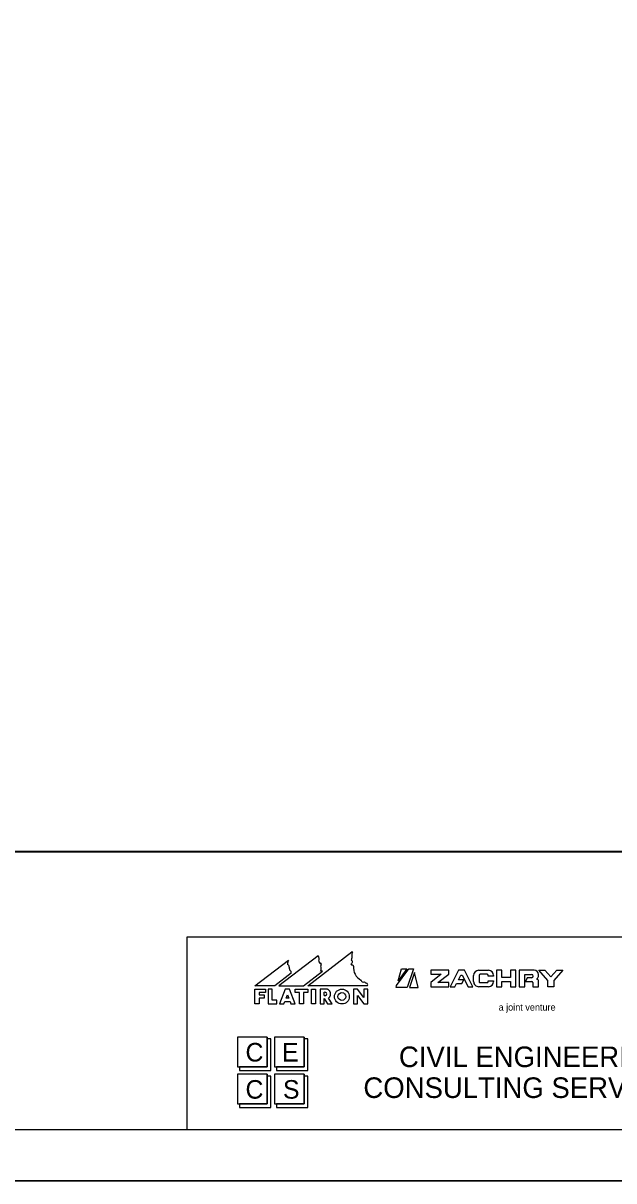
# Model space of a CAD drawing. Extents: x -2251 to 10196, y -13470 to 1199.
# Drawn here: x 6234 to 6521, y -10426 to -9863 of the extents above; entities that cross this region are included whole.
import ezdxf

# ---------------------------------------------------------------- set-up
doc = ezdxf.new("R2010")
doc.units = 0
for name, color, linetype in [('Level 3', 7, 'Continuous'), ('RD_SHT_Bndy', 7, 'Continuous'), ('RD_SHT_Iplotshp', 7, 'Continuous'), ('RD_SHT_Logo', 7, 'Continuous'), ('RD_SHT_Misc1', 7, 'Continuous'), ('RD_SHT_Snap', 7, 'Continuous'), ('RD_SHT_TX', 7, 'Continuous'), ('RD_TX_RoadID', 7, 'Continuous')]:
    doc.layers.add(name, color=color, linetype=linetype)

msp = doc.modelspace()

# ---------------------------------------------------------------- linework, layer by layer
at = {"layer": 'Level 3'}
msp.add_line((6465.07, -10363.99), (6465.07, -10363.99), dxfattribs=at)
msp.add_line((6465.07, -10363.99), (6465.07, -10363.99), dxfattribs=at)
msp.add_line((6465.07, -10363.99), (6465.07, -10363.99), dxfattribs=at)
msp.add_line((6465.07, -10363.99), (6465.07, -10363.99), dxfattribs=at)
at = {"layer": 'RD_SHT_Bndy'}
for p, q in [((5103.1, -10400.65), (6778.1, -10400.65)), ((6791.65, -10425.65), (5031.65, -10425.65))]:
    msp.add_line(p, q, dxfattribs=at)
msp.add_lwpolyline([(5153.4, -9401.26), (6731.08, -9401.26), (6731.08, -10265.57), (5153.4, -10265.57)], close=True, dxfattribs=at)
at = {"layer": 'RD_SHT_Iplotshp'}
msp.add_lwpolyline([(4996.65, -9325.65), (6796.65, -9325.65), (6796.65, -10425.65), (4996.65, -10425.65)], close=True, dxfattribs=at)
at = {"layer": 'RD_SHT_Logo'}
for p, q in [((6372.32, -10330.86), (6393.74, -10314.44)), ((6346.7, -10330.86), (6362.98, -10318.38)), ((6377.35, -10316.27), (6358.31, -10330.86)), ((6364.27, -10324.74), (6356.29, -10330.86)), ((6370.3, -10330.86), (6379.48, -10323.82)), ((6415.56, -10330.77), (6421.47, -10322.59)), ((6420.48, -10322.59), (6416.24, -10328.47)), ((6416.24, -10328.47), (6417.96, -10322.59)), ((6417.96, -10322.59), (6420.48, -10322.59)), ((6423.82, -10322.59), (6420.68, -10331.76)), ((6421.47, -10322.59), (6423.82, -10322.59)), ((6424.24, -10324.44), (6421.74, -10331.76)), ((6425.99, -10331.76), (6424.24, -10324.44)), ((6440.93, -10323.35), (6432.22, -10323.35)), ((6432.22, -10323.35), (6432.22, -10325.3)), ((6437.2, -10325.3), (6432.22, -10329.24)), ((6432.22, -10325.3), (6437.2, -10325.3)), ((6435.63, -10329.35), (6440.93, -10325.16)), ((6440.93, -10325.16), (6440.93, -10323.35)), ((6445.58, -10323.35), (6441.53, -10331.3)), ((6445.57, -10327.99), (6446.71, -10325.75)), ((6448.58, -10323.35), (6445.58, -10323.35)), ((6446.71, -10325.75), (6447.44, -10325.75)), ((6447.44, -10325.75), (6450.27, -10331.3)), ((6452.63, -10331.3), (6448.58, -10323.35)), ((6452.94, -10328.8), (6452.94, -10325.85)), ((6455.44, -10323.35), (6460.18, -10323.35)), ((6455.64, -10325.8), (6455.64, -10328.85)), ((6459.48, -10325.3), (6456.14, -10325.3)), ((6459.98, -10326.15), (6459.98, -10325.8)), ((6462.68, -10326.15), (6459.98, -10326.15)), ((6462.68, -10325.85), (6462.68, -10326.15)), ((6466.62, -10323.35), (6464.02, -10323.35)), ((6464.02, -10323.35), (6464.02, -10331.3)), ((6466.62, -10326.8), (6466.62, -10323.35)), ((6470.9, -10326.8), (6466.62, -10326.8)), ((6470.9, -10323.35), (6470.9, -10326.8)), ((6473.51, -10323.35), (6470.9, -10323.35)), ((6473.5, -10331.3), (6473.51, -10323.35)), ((6482.43, -10323.35), (6475.13, -10323.35)), ((6475.13, -10323.35), (6475.13, -10331.3)), ((6477.83, -10331.3), (6477.83, -10325.31)), ((6477.83, -10325.31), (6481.07, -10325.31)), ((6479.03, -10326.97), (6478.11, -10328.77)), ((6481.07, -10326.97), (6479.03, -10326.97)), ((6483.68, -10327.6), (6483.68, -10327.47)), ((6484.43, -10326.36), (6484.43, -10325.35)), ((6484.68, -10323.35), (6487.64, -10323.35)), ((6489.08, -10328.24), (6484.68, -10323.35)), ((6487.64, -10323.35), (6490.48, -10326.51)), ((6490.48, -10326.51), (6493.32, -10323.35)), ((6496.28, -10323.35), (6491.88, -10328.24)), ((6493.32, -10323.35), (6496.28, -10323.35)), ((6356.29, -10330.86), (6346.7, -10330.86)), ((6346.72, -10339.7), (6346.72, -10332.5)), ((6346.72, -10332.5), (6351.82, -10332.5)), ((6351.82, -10332.5), (6351.82, -10334.15)), ((6355.12, -10332.5), (6353.17, -10332.5)), ((6353.17, -10332.5), (6353.17, -10339.7)), ((6355.12, -10337.9), (6355.12, -10332.5)), ((6358.31, -10330.86), (6370.3, -10330.86)), ((6361.42, -10332.5), (6358.65, -10339.71)), ((6363.52, -10332.5), (6361.42, -10332.5)), ((6366.28, -10339.71), (6363.52, -10332.5)), ((6366.22, -10334.15), (6366.22, -10332.5)), ((6366.22, -10332.5), (6372.37, -10332.5)), ((6401.19, -10330.86), (6372.32, -10330.86)), ((6372.37, -10332.5), (6372.37, -10334.15)), ((6374.17, -10339.71), (6374.17, -10332.5)), ((6374.17, -10332.5), (6376.12, -10332.5)), ((6376.12, -10332.5), (6376.12, -10339.71)), ((6381.8, -10332.5), (6378.38, -10332.5)), ((6378.38, -10332.5), (6378.38, -10339.71)), ((6396.52, -10332.5), (6394.57, -10332.5)), ((6394.57, -10332.5), (6394.57, -10339.71)), ((6399.67, -10336.53), (6396.52, -10332.5)), ((6401.62, -10332.5), (6399.67, -10332.5)), ((6399.67, -10332.5), (6399.67, -10336.53)), ((6401.62, -10339.71), (6401.62, -10332.5)), ((6415.27, -10331.76), (6415.56, -10330.77)), ((6420.68, -10331.76), (6415.27, -10331.76)), ((6421.74, -10331.76), (6425.99, -10331.76)), ((6432.22, -10329.24), (6432.22, -10331.3)), ((6432.22, -10331.3), (6440.93, -10331.3)), ((6440.93, -10329.35), (6435.63, -10329.35)), ((6440.93, -10331.3), (6440.93, -10329.35)), ((6441.53, -10331.3), (6443.88, -10331.3)), ((6443.88, -10331.3), (6444.65, -10329.79)), ((6444.65, -10329.79), (6447.23, -10329.79)), ((6448.15, -10327.99), (6445.57, -10327.99)), ((6447.23, -10329.79), (6448.15, -10327.99)), ((6450.27, -10331.3), (6452.63, -10331.3)), ((6460.18, -10331.3), (6455.44, -10331.3)), ((6456.14, -10329.35), (6459.48, -10329.35)), ((6459.98, -10328.5), (6462.68, -10328.5)), ((6459.98, -10328.85), (6459.98, -10328.5)), ((6462.68, -10328.5), (6462.68, -10328.8)), ((6464.02, -10331.3), (6466.62, -10331.3)), ((6466.62, -10331.3), (6466.62, -10328.8)), ((6466.62, -10328.8), (6470.9, -10328.8)), ((6470.9, -10328.8), (6470.9, -10331.3)), ((6470.9, -10331.3), (6473.5, -10331.3)), ((6475.13, -10331.3), (6477.83, -10331.3)), ((6478.11, -10328.77), (6481.24, -10328.77)), ((6481.74, -10329.27), (6481.74, -10331.3)), ((6481.74, -10331.3), (6484.54, -10331.3)), ((6484.54, -10331.3), (6484.54, -10328.76)), ((6489.08, -10331.3), (6489.08, -10328.24)), ((6491.88, -10331.3), (6489.08, -10331.3)), ((6491.88, -10328.24), (6491.88, -10331.3)), ((6351.82, -10334.15), (6348.67, -10334.15)), ((6348.67, -10334.15), (6348.67, -10335.21)), ((6348.67, -10335.21), (6351.22, -10335.21)), ((6351.22, -10336.86), (6348.67, -10336.86)), ((6348.67, -10336.86), (6348.67, -10339.7)), ((6351.22, -10335.21), (6351.22, -10336.86)), ((6357.37, -10337.9), (6355.12, -10337.9)), ((6357.37, -10339.71), (6357.37, -10337.9)), ((6360.74, -10339.71), (6361.2, -10338.51)), ((6361.2, -10338.51), (6363.74, -10338.51)), ((6361.83, -10336.86), (6362.47, -10335.2)), ((6363.1, -10336.86), (6361.83, -10336.86)), ((6362.47, -10335.2), (6363.1, -10336.86)), ((6363.74, -10338.51), (6364.2, -10339.71)), ((6368.32, -10334.15), (6366.22, -10334.15)), ((6368.32, -10339.71), (6368.32, -10334.15)), ((6372.37, -10334.15), (6370.27, -10334.15)), ((6370.27, -10334.15), (6370.27, -10339.71)), ((6380.33, -10335.66), (6380.33, -10334.01)), ((6380.33, -10339.71), (6380.33, -10337.02)), ((6380.33, -10337.02), (6381.94, -10339.71)), ((6384.16, -10339.71), (6382.43, -10336.82)), ((6396.52, -10339.71), (6396.52, -10335.67)), ((6396.52, -10335.67), (6399.67, -10339.71)), ((6348.67, -10339.7), (6346.72, -10339.7)), ((6353.17, -10339.7), (6357.37, -10339.71)), ((6358.65, -10339.71), (6360.74, -10339.71)), ((6364.2, -10339.71), (6366.28, -10339.71)), ((6370.27, -10339.71), (6368.32, -10339.71)), ((6376.12, -10339.71), (6374.17, -10339.71)), ((6378.38, -10339.71), (6380.33, -10339.71)), ((6381.94, -10339.71), (6384.16, -10339.71)), ((6394.57, -10339.71), (6396.52, -10339.71)), ((6399.67, -10339.71), (6401.62, -10339.71)), ((6352.67, -10355.79), (6338.28, -10355.79)), ((6338.28, -10355.79), (6338.28, -10370.23)), ((6352.67, -10370.23), (6352.67, -10355.79)), ((6352.67, -10355.79), (6352.67, -10370.23)), ((6354.48, -10356.7), (6352.67, -10356.7)), ((6354.48, -10372.03), (6354.48, -10356.7)), ((6370.67, -10355.79), (6356.27, -10355.79)), ((6356.27, -10355.79), (6356.27, -10370.23)), ((6370.67, -10370.23), (6370.67, -10355.79)), ((6370.67, -10355.79), (6370.67, -10370.23)), ((6372.48, -10356.7), (6370.67, -10356.7)), ((6372.48, -10372.03), (6372.48, -10356.7)), ((6338.28, -10370.23), (6352.67, -10370.23)), ((6352.67, -10370.23), (6339.17, -10370.23)), ((6339.17, -10370.23), (6339.17, -10372.03)), ((6339.17, -10372.03), (6354.48, -10372.03)), ((6356.27, -10370.23), (6370.67, -10370.23)), ((6370.67, -10370.23), (6357.18, -10370.23)), ((6357.18, -10370.23), (6357.18, -10372.03)), ((6357.18, -10372.03), (6372.48, -10372.03)), ((6352.67, -10373.84), (6338.28, -10373.84)), ((6338.28, -10373.84), (6338.28, -10388.27)), ((6352.67, -10388.27), (6352.67, -10373.84)), ((6352.67, -10373.84), (6352.67, -10388.27)), ((6354.48, -10374.74), (6352.67, -10374.74)), ((6354.48, -10390.07), (6354.48, -10374.74)), ((6370.67, -10373.84), (6356.27, -10373.84)), ((6356.27, -10373.84), (6356.27, -10388.27)), ((6370.67, -10388.27), (6370.67, -10373.84)), ((6370.67, -10373.84), (6370.67, -10388.27)), ((6372.48, -10374.74), (6370.67, -10374.74)), ((6372.48, -10390.07), (6372.48, -10374.74)), ((6338.28, -10388.27), (6352.67, -10388.27)), ((6352.67, -10388.27), (6339.17, -10388.27)), ((6339.17, -10388.27), (6339.17, -10390.07)), ((6356.27, -10388.27), (6370.67, -10388.27)), ((6370.67, -10388.27), (6357.18, -10388.27)), ((6357.18, -10388.27), (6357.18, -10390.07)), ((6339.17, -10390.07), (6354.48, -10390.07)), ((6357.18, -10390.07), (6372.48, -10390.07))]:
    msp.add_line(p, q, dxfattribs=at)
for radius in [3.6, 1.9]:
    msp.add_circle((6388.95, -10336.1), radius, dxfattribs=at)
for centre, radius, start, end in [((6397.87, -10316.34), 4.17, 156.4699, 195.3053), ((6393.86, -10314.6), 0.2, 336.4699, 127.4657), ((6366.29, -10320.12), 3.74, 152.2252, 185.8662), ((6362.1, -10321.62), 1.21, 351.6466, 67.1294), ((6364.29, -10321.94), 1, 171.6466, 221.9371), ((6375.05, -10318.02), 2.89, 342.0343, 37.2653), ((6377.99, -10318.97), 0.2, 162.0343, 220.8638), ((6376.86, -10319.95), 1.3, 11.8745, 40.8638), ((6378.32, -10319.64), 0.2, 191.8745, 279.8173), ((6378.44, -10320.33), 0.499, 44.4799, 99.8173), ((6375.8, -10322.18), 3.16, 331.2486, 18.4584), ((6379.5, -10320.72), 0.843, 144.641, 212.5499), ((6378.65, -10320.12), 0.2, 324.641, 44.4799), ((6393.57, -10320.5), 0.2, 133.0036, 262.3069), ((6391.59, -10318.37), 2.7, 313.0036, 343.6807), ((6393.73, -10318.39), 0.2, 129.4079, 246.863), ((6393.31, -10322.44), 1.76, 45.283, 82.3069), ((6393.13, -10317.66), 0.749, 309.4079, 17.0499), ((6393.27, -10319.47), 0.973, 20.4113, 66.863), ((6394.4, -10321.33), 0.2, 353.8329, 45.283), ((6401.36, -10322.08), 6.8, 173.8329, 242.3928), ((6363.11, -10323.01), 0.592, 327.6019, 41.9371), ((6363.3, -10324.33), 1.05, 337.4201, 73.1261), ((6378.92, -10324.44), 0.827, 48.0701, 115.7229), ((6455.44, -10325.85), 2.5, 89.9984, 179.9984), ((6456.14, -10325.8), 0.5, 89.9984, 179.9984), ((6459.48, -10325.8), 0.5, 359.9984, 89.9984), ((6460.18, -10325.85), 2.5, 359.9984, 89.9984), ((6481.07, -10326.14), 0.831, 269.9984, 89.9984), ((6482.43, -10325.35), 2, 359.9984, 89.9984), ((6483.23, -10326.36), 1.2, 291.95, 359.9984), ((6398.12, -10328.28), 0.2, 9.0833, 62.3928), ((6399.35, -10328.09), 1.04, 189.0833, 295.769), ((6399.89, -10329.21), 0.2, 33.7112, 115.769), ((6400.89, -10328.54), 1.01, 213.7112, 268.6299), ((6400.86, -10329.74), 0.2, 78.9712, 88.6299), ((6400.75, -10330.3), 0.767, 320.912, 78.9712), ((6401.19, -10330.66), 0.2, 269.9984, 320.912), ((6455.44, -10328.8), 2.5, 179.9984, 269.9984), ((6456.14, -10328.85), 0.5, 179.9984, 269.9984), ((6459.48, -10328.85), 0.5, 269.9984, 359.9984), ((6460.18, -10328.8), 2.5, 269.9984, 359.9984), ((6481.24, -10329.27), 0.5, 359.9984, 89.9984), ((6483.34, -10328.76), 1.2, 359.9984, 73.7977)]:
    msp.add_arc(centre, radius, start, end, dxfattribs=at)
msp.add_ellipse((6380.33, -10334.83), major_axis=(1.36, 0), ratio=0.609965, start_param=4.712389, end_param=7.853982, dxfattribs=at)
msp.add_open_spline([(6382.43, -10336.82), (6382.51, -10336.76), (6382.59, -10336.7), (6382.81, -10336.49), (6382.95, -10336.34), (6383.13, -10336.07), (6383.19, -10335.97), (6383.29, -10335.77), (6383.34, -10335.66), (6383.41, -10335.44), (6383.44, -10335.32), (6383.47, -10335.08), (6383.48, -10334.96), (6383.48, -10334.71), (6383.47, -10334.59), (6383.44, -10334.35), (6383.41, -10334.23), (6383.34, -10334.01), (6383.29, -10333.9), (6383.19, -10333.7), (6383.13, -10333.6), (6382.95, -10333.33), (6382.81, -10333.18), (6382.52, -10332.91), (6382.37, -10332.8), (6382.08, -10332.63), (6381.94, -10332.56), (6381.8, -10332.5)], degree=3, dxfattribs=at)
at = {"layer": 'RD_SHT_Misc1'}
msp.add_lwpolyline([(6796.65, -10425.65), (6796.68, -9325.65), (5096.68, -9325.6), (5096.65, -10425.6)], close=True, dxfattribs=at)
at = {"layer": 'RD_SHT_Snap'}
msp.add_lwpolyline([(5008.15, -9325.65), (6808.15, -9325.65), (6808.15, -10425.65), (5008.15, -10425.65)], close=True, dxfattribs=at)
at = {"layer": 'RD_SHT_TX'}
for p, q in [((6313.76, -10400.65), (6313.76, -10307.15)), ((6313.76, -10400.65), (6313.76, -10307.15)), ((6313.76, -10307.15), (6778.1, -10307.15))]:
    msp.add_line(p, q, dxfattribs=at)
at = {"layer": 'RD_TX_RoadID'}
msp.add_lwpolyline([(5150.54, -10265.73), (6733.93, -10265.73), (6733.93, -9462.61), (5150.54, -9462.61)], close=True, dxfattribs=at)

# ---------------------------------------------------------------- texts
at = {"layer": 'RD_SHT_Logo'}
msp.add_text('a joint venture', height=3.3, rotation=359.9984, dxfattribs=at).set_placement((6465.08, -10342.93))
for s, height, p in [('C', 9.02, (6342.11, -10367.66)), ('E', 9.02, (6359.9, -10367.66)), ('CIVIL ENGINEERING', 10, (6416.67, -10370.38)), ('C', 9.02, (6342.11, -10385.71)), ('S', 9.02, (6360.32, -10385.71)), ('CONSULTING SERVICES, INC.', 10, (6399.39, -10385.38))]:
    msp.add_text(s, height=height, dxfattribs=at).set_placement(p)

doc.saveas('drawing.dxf')
